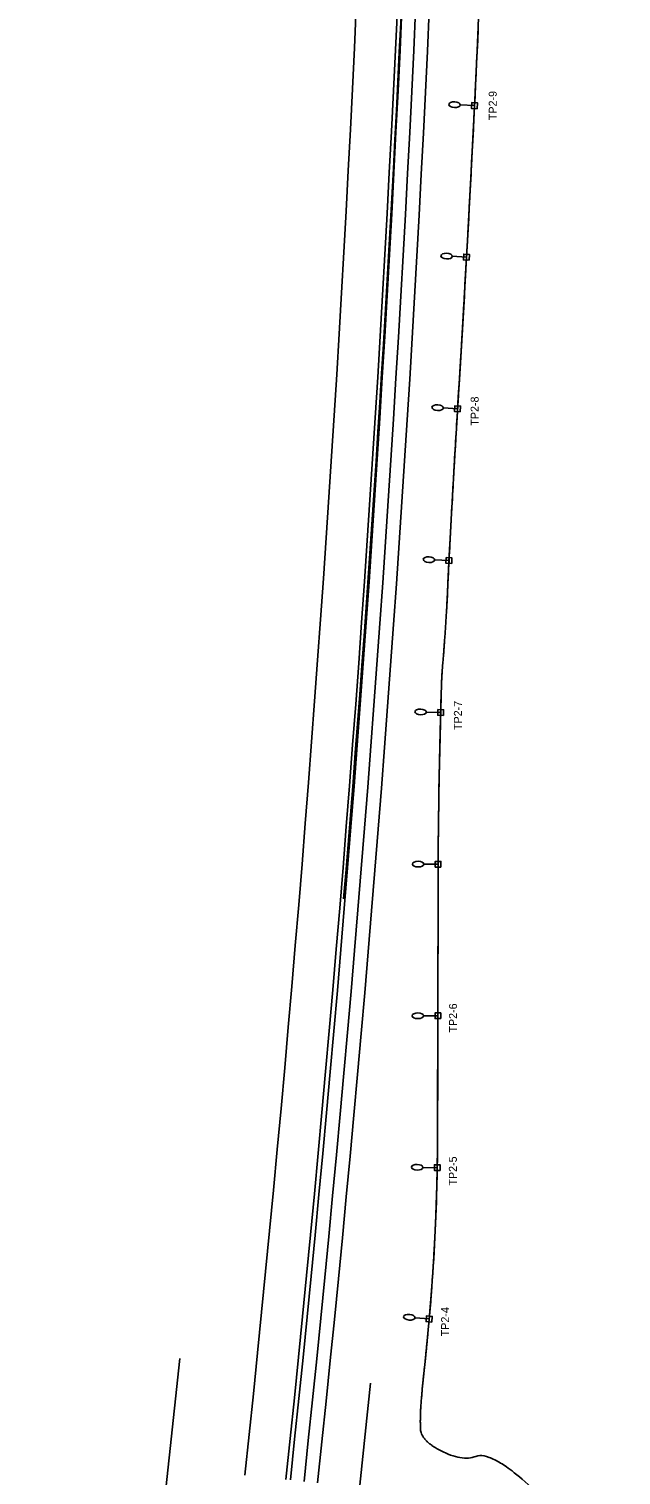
# Model space of a CAD drawing. Extents: x 172067 to 172728, y 250510 to 260293.
# Drawn here: x 172203 to 172721, y 256085 to 257350 of the extents above; entities that cross this region are included whole.
import ezdxf

# ---------------------------------------------------------------- set-up
doc = ezdxf.new("R2010")
doc.units = 0
for name, color, linetype in [('_CIVIL_CONSTRUCTION', 7, 'Continuous'), ('CM_Corridor_Final', 7, 'Continuous'), ('DR_P_Ditch', 7, 'Continuous'), ('MD_P_ACSC_T', 7, 'Continuous'), ('MD_P_Surface_Aggregate_Base', 7, 'Continuous'), ('MD_P_Surface_Ditch', 7, 'Continuous'), ('MD_P_Surface_Finished_Grade', 7, 'Continuous'), ('SC_Scratch1', 7, 'Continuous')]:
    doc.layers.add(name, color=color, linetype=linetype)

msp = doc.modelspace()

# ---------------------------------------------------------------- linework, layer by layer
at = {"layer": '_CIVIL_CONSTRUCTION'}
msp.add_line((172202.7, 254942.7), (172334.7, 256186.9), dxfattribs=at)
msp.add_arc((151025.4, 258373.7), 21526.9, 355.24419, 359.60258, dxfattribs=at)
at = {"layer": 'CM_Corridor_Final'}
for p, q in [((172592.8, 257282.5), (172580.3, 257283.1)), ((172585.8, 257150), (172573.3, 257150.7)), ((172578, 257017.3), (172565.5, 257018.1)), ((172570.4, 256884.7), (172557.9, 256885.3)), ((172563.1, 256751.8), (172550.6, 256752.1)), ((172560.9, 256619.1), (172548.4, 256619.2)), ((172560.7, 256486.6), (172548.2, 256486.6)), ((172560.1, 256353.7), (172547.6, 256354)), ((172553.1, 256221.5), (172540.7, 256222.5))]:
    msp.add_line(p, q, dxfattribs=at)
for points in [[(172595.1, 257279.8), (172590.1, 257280.1), (172590.4, 257285.1), (172595.4, 257284.8)], [(172588.1, 257147.3), (172583.1, 257147.6), (172583.4, 257152.6), (172588.4, 257152.3)], [(172580.3, 257014.7), (172575.3, 257015), (172575.6, 257020), (172580.6, 257019.7)], [(172572.8, 256882), (172567.8, 256882.3), (172568, 256887.3), (172573, 256887)], [(172565.6, 256749.2), (172560.6, 256749.4), (172560.7, 256754.4), (172565.7, 256754.2)], [(172563.4, 256616.6), (172558.4, 256616.6), (172558.4, 256621.6), (172563.4, 256621.6)], [(172563.2, 256484.1), (172558.2, 256484.1), (172558.2, 256489.1), (172563.2, 256489.1)], [(172562.6, 256351.2), (172557.6, 256351.3), (172557.7, 256356.3), (172562.7, 256356.2)], [(172555.4, 256218.7), (172550.4, 256219.2), (172550.8, 256224.2), (172555.8, 256223.7)]]:
    msp.add_lwpolyline(points, close=True, dxfattribs=at)
for centre, major_axis in [((172575.3, 257283.3), (-4.99, 0.25)), ((172568.3, 257150.9), (-4.99, 0.28)), ((172560.5, 257018.4), (-4.99, 0.3)), ((172552.9, 256885.5), (-4.99, 0.25)), ((172545.6, 256752.3), (-5, 0.14)), ((172543.4, 256619.2), (-5, 0.02)), ((172543.2, 256486.6), (-5, 0.01)), ((172542.6, 256354.1), (-5, 0.09)), ((172535.7, 256223), (-4.98, 0.44))]:
    msp.add_ellipse(centre, major_axis=major_axis, ratio=0.5, dxfattribs=at)
at = {"layer": 'DR_P_Ditch'}
for points in [[(172592.8, 257282.5), (172593.2, 257291.3), (172594.5, 257318.9), (172595.7, 257344.1), (172596.3, 257360.2), (172596.8, 257380.5), (172597.4, 257406.3), (172597.8, 257422.5), (172598.1, 257437.6), (172598.5, 257453.7), (172598.7, 257463.4), (172599.1, 257481.4), (172599.5, 257502.1), (172599.9, 257524.1), (172600.1, 257534.9), (172600.3, 257548.1)], [(172578, 257017.3), (172578.6, 257027.7), (172580.1, 257051.8), (172581.7, 257078.8), (172582.7, 257095.8), (172583.7, 257113.8), (172584.7, 257131.2), (172585.2, 257140), (172586.3, 257158.9), (172588.1, 257192.9), (172589.5, 257218.5), (172591.2, 257252), (172592.4, 257275.3), (172592.8, 257282.5)], [(172563.1, 256751.8), (172563.4, 256762.4), (172563.8, 256774.1), (172564.2, 256785), (172565.9, 256805.6), (172567.1, 256822.1), (172568.3, 256840.5), (172569.2, 256858.8), (172569.9, 256875.3), (172570.7, 256891.2), (172571.6, 256906.8), (172572.7, 256927.4), (172574.3, 256955.8), (172575.6, 256978.2), (172576.9, 256999), (172577.3, 257005.9), (172578, 257017.3)], [(172560.7, 256486.6), (172560.7, 256495), (172560.7, 256503.4), (172560.7, 256514), (172560.7, 256522.9), (172560.8, 256537.5), (172560.8, 256547.7), (172560.8, 256554.4), (172560.8, 256560.6), (172560.8, 256574.4), (172560.9, 256587.9), (172560.9, 256597.4), (172560.9, 256609.2), (172560.9, 256615.5), (172561, 256623.6), (172561, 256636.1), (172561.1, 256644.9), (172561.3, 256659), (172561.5, 256674.8), (172561.7, 256688.6), (172562, 256704.7), (172562.4, 256721.7), (172562.7, 256735.4), (172563, 256745.7), (172563.1, 256751.8)], [(172560.1, 256353.7), (172560.3, 256368), (172560.4, 256380.9), (172560.5, 256389.9), (172560.5, 256415.4), (172560.6, 256433), (172560.6, 256443.3), (172560.6, 256460.3), (172560.6, 256471.8), (172560.6, 256478.9), (172560.7, 256486.6)], [(172553.1, 256221.5), (172554.2, 256234.5), (172555.4, 256249.7), (172556.6, 256267), (172557.4, 256281.3), (172558.3, 256297.9), (172558.9, 256311.9), (172559.5, 256330.1), (172559.8, 256337.9), (172560, 256346.2), (172560.1, 256353.7)], [(172714.2, 255913.4), (172715.8, 255927.8), (172718.3, 255952.1), (172720.5, 255972.2), (172721.4, 255980.9), (172715.6, 255996.3), (172653.7, 256066), (172604.6, 256105.5), (172581.8, 256096.8), (172546, 256114.9), (172545, 256135.4), (172547, 256160.5), (172547.5, 256165.1), (172549.8, 256187), (172551.6, 256205.1), (172553.1, 256221.5)]]:
    msp.add_open_spline(points, degree=2, dxfattribs=at)
at = {"layer": 'MD_P_ACSC_T'}
for p, q in [((172560.9, 256601.7), (172560.5, 256386)), ((172549.8, 256187), (172546.9, 256160.4)), ((172429.4, 255482.4), (172501.7, 256165.2))]:
    msp.add_line(p, q, dxfattribs=at)
for centre, radius, start, end in [((151025.9, 258352.5), 21593.4, 356.51058, 357.33743), ((178276, 256590.8), 5715.1, 178.0108, 179.8908), ((170636.1, 256389.7), 1924.4, 353.955, 359.8908)]:
    msp.add_arc(centre, radius, start, end, dxfattribs=at)
msp.add_open_spline([(172579.2, 257038.2), (172578.2, 257021.6), (172577.2, 257005), (172575.2, 256971.7), (172574.3, 256955.1), (172572.4, 256921.9), (172571.5, 256905.3), (172569.8, 256872), (172569, 256855.4), (172568.3, 256838.8)], degree=3, dxfattribs=at)
at = {"layer": 'MD_P_Surface_Aggregate_Base'}
msp.add_arc((151025.9, 258352.5), 21521.9, 353.94188, 0.0466, dxfattribs=at)
at = {"layer": 'MD_P_Surface_Ditch'}
msp.add_arc((151025.9, 258352.5), 21537.9, 353.94188, 0.0466, dxfattribs=at)
at = {"layer": 'MD_P_Surface_Finished_Grade'}
for radius in [21525.9, 21549.9]:
    msp.add_arc((151025.9, 258352.5), radius, 353.94188, 0.0466, dxfattribs=at)
at = {"layer": 'SC_Scratch1'}
msp.add_arc((151025.9, 258352.5), 21485.9, 353.94188, 0.0466, dxfattribs=at)
msp.add_arc((151025.9, 258352.5), 21485.9, 353.94188, 0.0466, dxfattribs=at)
msp.add_arc((151025.9, 258352.5), 21485.9, 353.94188, 0.0466, dxfattribs=at)
msp.add_arc((151025.9, 258352.5), 21485.9, 353.94188, 0.0466, dxfattribs=at)

# ---------------------------------------------------------------- texts
at = {"layer": 'MD_P_ACSC_T'}
for s, p in [('TP2-9', (172612.2, 257269.8)), ('TP2-8', (172596.4, 257002.6)), ('TP2-7', (172581.7, 256736.5)), ('TP2-6', (172577.4, 256471.9)), ('TP2-5', (172577.3, 256338.1)), ('TP2-4', (172570.5, 256206.3))]:
    msp.add_text(s, height=7, rotation=89.9803, dxfattribs=at).set_placement(p)

doc.saveas('drawing.dxf')
